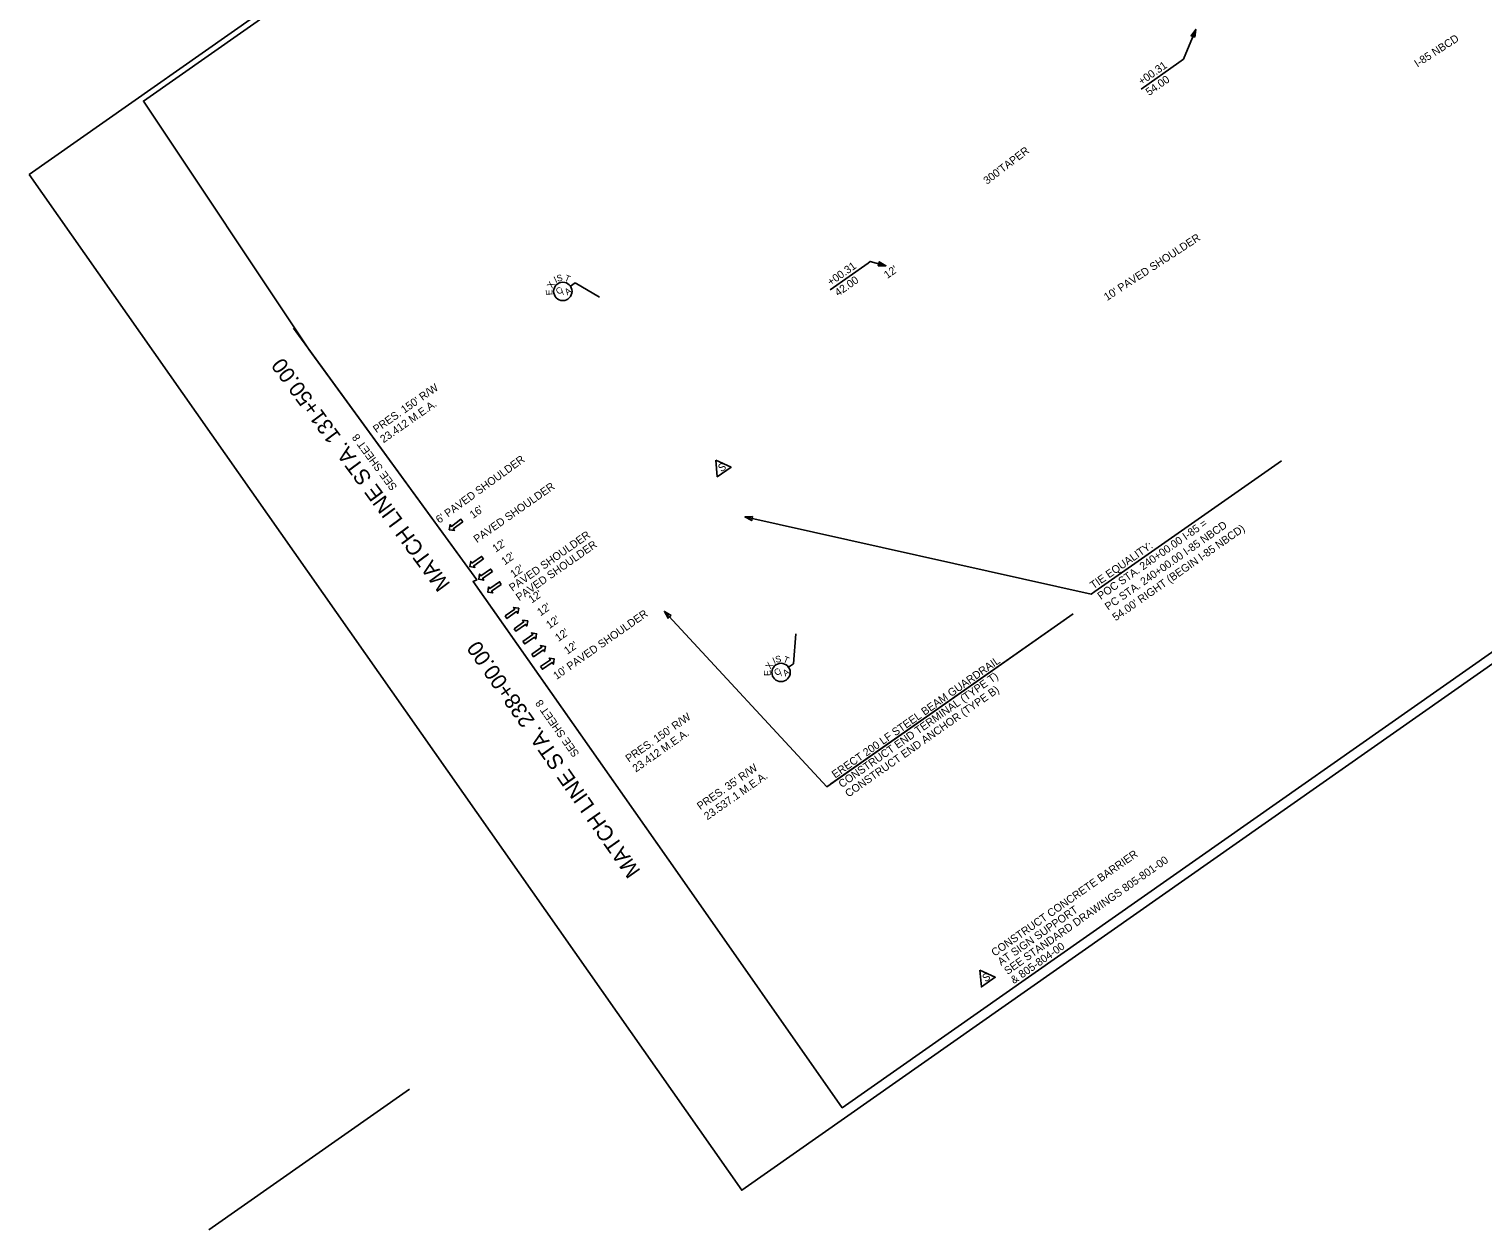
# Model space of a CAD drawing. Extents: x 1606191 to 1608111, y 1090371 to 1092208.
# Drawn here: x 1606191 to 1607311, y 1090371 to 1091296 of the extents above; entities that cross this region are included whole.
import ezdxf

# ---------------------------------------------------------------- set-up
doc = ezdxf.new("R2010")
doc.units = 0
for name, color, linetype in [('Copy of RD_HC_SUR_CL200', 7, 'Continuous'), ('Copy of RD_HC_SUR_DATA_200', 7, 'Continuous'), ('RD_EX_BldgApp', 7, 'Continuous'), ('RD_EX_Fence_Other', 7, 'Continuous'), ('RD_EX_Misc', 7, 'Continuous'), ('RD_EX_Misc_Golf_Teebox', 7, 'Continuous'), ('RD_EX_TopoTX', 7, 'Continuous'), ('RD_EX_VEG', 7, 'Continuous'), ('RD_TX_DR_Pipe', 7, 'Continuous'), ('V-BLDG-OTLN', 7, 'Continuous')]:
    doc.layers.add(name, color=color, linetype=linetype)

msp = doc.modelspace()

# ---------------------------------------------------------------- linework, layer by layer
at = {"layer": 'Copy of RD_HC_SUR_CL200'}
for p, q in [((1606608, 1091098.2), (1606611.8, 1091100.8)), ((1606611.8, 1091100.8), (1606630.5, 1091089.6)), ((1606779.9, 1090807.1), (1606781.9, 1090830.3)), ((1606776.2, 1090804.4), (1606779.9, 1090807.1))]:
    msp.add_line(p, q, dxfattribs=at)
for centre in [(1606602.2, 1091094.1), (1606770.4, 1090800.4)]:
    msp.add_circle(centre, 7.08, dxfattribs=at)
at = {"layer": 'Copy of RD_HC_SUR_DATA_200'}
msp.add_line((1606995.6, 1090845.5), (1606808.9, 1090714.5), dxfattribs=at)
msp.add_lwpolyline([(1606995.6, 1090845.5), (1606805.8, 1090712.3), (1606680.5, 1090847.5)], dxfattribs=at)
msp.add_lwpolyline([(1606685.6, 1090844.3), (1606680.5, 1090847.5), (1606683.3, 1090842.2)], close=True, dxfattribs=at)
at = {"layer": 'RD_EX_Fence_Other'}
msp.add_lwpolyline([(1606190.8, 1091184.3), (1607562.1, 1092146.2), (1608111.3, 1091363.1), (1606740.1, 1090401.3)], close=True, dxfattribs=at)
at = {"layer": 'RD_EX_Misc'}
for points in [[(1606525.1, 1090916.5), (1606523.7, 1090918.5), (1606516.3, 1090913), (1606515.3, 1090914.4), (1606514.7, 1090910.4), (1606518.7, 1090909.8), (1606517.7, 1090911.1)], [(1606541, 1090888), (1606539.6, 1090889.9), (1606532.1, 1090884.7), (1606531.2, 1090886), (1606530.5, 1090882), (1606534.4, 1090881.4), (1606533.5, 1090882.7)], [(1606547.9, 1090878.1), (1606546.5, 1090880.1), (1606539, 1090874.8), (1606538.1, 1090876.2), (1606537.4, 1090872.2), (1606541.3, 1090871.5), (1606540.4, 1090872.9)], [(1606554.8, 1090868.3), (1606553.4, 1090870.3), (1606545.9, 1090865), (1606545, 1090866.3), (1606544.3, 1090862.4), (1606548.2, 1090861.7), (1606547.3, 1090863)], [(1606557.7, 1090844), (1606559.1, 1090842), (1606566.6, 1090847.3), (1606567.5, 1090845.9), (1606568.2, 1090849.9), (1606564.3, 1090850.6), (1606565.2, 1090849.2)], [(1606564.6, 1090834.1), (1606566, 1090832.2), (1606573.5, 1090837.5), (1606574.4, 1090836.1), (1606575.1, 1090840.1), (1606571.2, 1090840.7), (1606572.1, 1090839.4)], [(1606571.5, 1090824.3), (1606572.8, 1090822.4), (1606580.4, 1090827.6), (1606581.3, 1090826.3), (1606582, 1090830.2), (1606578, 1090830.9), (1606579, 1090829.6)], [(1606578.4, 1090814.5), (1606579.7, 1090812.5), (1606587.2, 1090817.8), (1606588.2, 1090816.5), (1606588.9, 1090820.4), (1606584.9, 1090821.1), (1606585.9, 1090819.8)], [(1606585.1, 1090804.9), (1606586.5, 1090802.9), (1606594, 1090808.2), (1606595, 1090806.8), (1606595.6, 1090810.8), (1606591.7, 1090811.5), (1606592.6, 1090810.1)]]:
    msp.add_lwpolyline(points, close=True, dxfattribs=at)
at = {"layer": 'RD_EX_Misc_Golf_Teebox'}
for p, q in [((1607077.1, 1091270.6), (1607047.9, 1091250)), ((1606837.5, 1091115.9), (1606808.2, 1091095.4)), ((1607156.1, 1090963.6), (1607012.3, 1090862.8))]:
    msp.add_line(p, q, dxfattribs=at)
for points in [[(1607077.1, 1091270.6), (1607080.5, 1091273), (1607090, 1091296)], [(1606837.5, 1091115.9), (1606839.2, 1091117.2), (1606851.3, 1091113.9)], [(1607012.3, 1090862.8), (1607009.5, 1090860.8), (1606742.5, 1090920.3)]]:
    msp.add_lwpolyline(points, dxfattribs=at)
for points in [[(1607089.3, 1091290), (1607090, 1091296), (1607086.4, 1091291.2)], [(1606845.3, 1091113.9), (1606851.3, 1091113.9), (1606846.1, 1091116.9)], [(1606720.1, 1090964.1), (1606721.2, 1090951.2), (1606731.9, 1090958.6)], [(1606748.5, 1090920.5), (1606742.5, 1090920.3), (1606747.8, 1090917.5)], [(1606923.7, 1090571), (1606924.9, 1090558), (1606935.5, 1090565.5)]]:
    msp.add_lwpolyline(points, close=True, dxfattribs=at)
at = {"layer": 'RD_EX_VEG'}
msp.add_line((1606535.9, 1090871.8), (1606394.5, 1091065.7), dxfattribs=at)
msp.add_lwpolyline([(1606692.3, 1090643.6), (1606547.7, 1090849.6), (1606533, 1090870.5)], dxfattribs=at)
at = {"layer": 'RD_TX_DR_Pipe'}
msp.add_line((1606329.4, 1090370.8), (1606484.1, 1090479.3), dxfattribs=at)
at = {"layer": 'V-BLDG-OTLN'}
msp.add_lwpolyline([(1606406.7, 1091049.1), (1606535.9, 1090871.8), (1606533, 1090870.5), (1606692.3, 1090643.6), (1606817.6, 1090464.9), (1608054.2, 1091332.3), (1607913.9, 1091514), (1607741.1, 1091760.4), (1607743.5, 1091761.6), (1607623.7, 1091926), (1607395.6, 1091983.6), (1607376.3, 1092010.2), (1606278.9, 1091240.8)], close=True, dxfattribs=at)
msp.add_lwpolyline([(1606406.7, 1091049.1), (1606535.9, 1090871.8), (1606533, 1090870.5), (1606692.3, 1090643.6), (1606817.6, 1090464.9), (1608054.2, 1091332.3), (1607913.9, 1091514), (1607741.1, 1091760.4), (1607743.5, 1091761.6), (1607623.7, 1091926), (1607395.6, 1091983.6), (1607376.3, 1092010.2), (1606278.9, 1091240.8)], close=True, dxfattribs=at)

# ---------------------------------------------------------------- texts
at = {"layer": 'Copy of RD_HC_SUR_CL200'}
for s, rotation, p in [('I', 24.9789, (1606596.7, 1091100.5)), ('S', 13.2584, (1606598.1, 1091101.5)), ('T', 338.0969, (1606603, 1091102.5)), ('E', 93.6275, (1606594.3, 1091091.3)), ('X', 60.1403, (1606594, 1091096.1)), ('C', 35.0436, (1606598.9, 1091091.3)), ('/', 35.0436, (1606602.5, 1091091.3)), ('A', 35.0436, (1606605.7, 1091090.9)), ('I', 23.0267, (1606765.1, 1090806.9)), ('S', 11.3062, (1606766.5, 1090807.8)), ('T', 336.1448, (1606771.5, 1090808.7)), ('E', 91.6753, (1606762.4, 1090797.8)), ('X', 58.1882, (1606762.3, 1090802.6)), ('C', 35.0436, (1606767.1, 1090797.5)), ('/', 35.0436, (1606770.7, 1090797.5)), ('A', 35.0436, (1606773.8, 1090797.1))]:
    msp.add_text(s, height=5, rotation=rotation, dxfattribs=at).set_placement(p)
at = {"layer": 'Copy of RD_HC_SUR_DATA_200'}
for s, p in [('ERECT 200 LF STEEL BEAM GUARDRAIL', (1606812.1, 1090718.6)), ('CONSTRUCT END TERMINAL (TYPE T)', (1606817.3, 1090711.2)), ('CONSTRUCT END ANCHOR (TYPE B)', (1606822.4, 1090703.9))]:
    msp.add_text(s, height=6, rotation=35.0485, dxfattribs=at).set_placement(p)
at = {"layer": 'RD_EX_BldgApp'}
for s, p in [("PRES. 150' R/W", (1606458.5, 1090984.7)), ('23.412 M.E.A.', (1606464, 1090977)), ("PRES. 150' R/W", (1606653.1, 1090730.9)), ('23.412 M.E.A.', (1606658.5, 1090723.2)), ("PRES. 35' R/W", (1606708.2, 1090694.2)), ('23.537.1 M.E.A.', (1606713.6, 1090686.4))]:
    msp.add_text(s, height=6, rotation=35.0468, dxfattribs=at).set_placement(p)
at = {"layer": 'RD_EX_Misc_Golf_Teebox'}
for s, rotation, p in [('+00.31', 35.0468, (1607048.3, 1091252.8)), ('54.00', 35.0468, (1607054.1, 1091244.6)), ("300'TAPER", 37.3374, (1606929.2, 1091176.2)), ("10' PAVED SHOULDER", 33.2265, (1607021.7, 1091086.6)), ('+00.31', 35.0468, (1606808.7, 1091098.2)), ("12'", 35.0436, (1606852.3, 1091103.6)), ('42.00', 35.0468, (1606814.4, 1091090)), ("6' PAVED SHOULDER", 36.0871, (1606507, 1090915)), ('S', 35.0468, (1606724.4, 1090954.6)), ('PAVED SHOULDER', 35.0468, (1606536, 1090900)), ("16'", 36.0638, (1606533.1, 1090918.7)), ('POC STA. 240+00.00 I-85 =', 35.0452, (1607016.9, 1090856.2)), ('PC STA. 240+00.00 I-85 NBCD', 35.0452, (1607022.6, 1090848)), ("54.00' RIGHT (BEGIN I-85 NBCD)", 35.0452, (1607028.4, 1090839.8)), ("12'", 35.0436, (1606550.5, 1090892.7)), ('PAVED SHOULDER', 35.0452, (1606563.4, 1090862.6)), ('PAVED SHOULDER', 35.0452, (1606568.6, 1090855.2)), ("12'", 35.0436, (1606557.4, 1090882.9)), ('TIE EQUALITY:', 35.0452, (1607011.2, 1090864.4)), ("12'", 35.0436, (1606564.3, 1090873.1)), ("12'", 35.0436, (1606578.3, 1090853.5)), ("12'", 35.0436, (1606585, 1090843.6)), ("10' PAVED SHOULDER", 35.0452, (1606597.4, 1090794.6)), ("12'", 35.0436, (1606591.9, 1090833.8)), ("12'", 35.0436, (1606598.8, 1090823.9)), ("12'", 35.0436, (1606605.7, 1090814)), ('CONSTRUCT CONCRETE BARRIER ', 35.0468, (1606935.1, 1090581.3)), ('SEE STANDARD DRAWINGS 805-801-00', 35.0468, (1606945, 1090567.2)), ('AT SIGN SUPPORT', 35.0468, (1606940, 1090574.2)), ('& 805-804-00', 35.0468, (1606949.9, 1090560.1)), ('S', 35.0468, (1606928.1, 1090561.5))]:
    msp.add_text(s, height=6, rotation=rotation, dxfattribs=at).set_placement(p)
at = {"layer": 'RD_EX_TopoTX'}
msp.add_text('I-85 NBCD', height=6, rotation=32.749, dxfattribs=at).set_placement((1607260.9, 1091266.6))
at = {"layer": 'RD_EX_VEG'}
for s, height, rotation, p in [('MATCH LINE STA. 131+50.00', 12, 126.4359, (1606515.9, 1090868.5)), ('SEE SHEET 8', 6, 126.4872, (1606474.8, 1090943.4)), ('MATCH LINE STA. 238+00.00', 12, 125.0468, (1606662.5, 1090647.4)), ('SEE SHEET 8', 6, 125.0981, (1606615.2, 1090737.8))]:
    msp.add_text(s, height=height, rotation=rotation, dxfattribs=at).set_placement(p)

doc.saveas('drawing.dxf')
